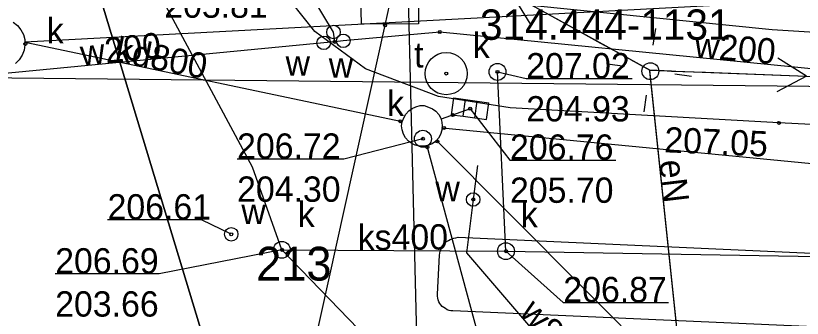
# Model space of a CAD drawing. Extents: x 6512606 to 6513347, y 6022524 to 6022728.
# Drawn here: x 6512795.99 to 6512819.3, y 6022679.94 to 6022688.9 of the extents above; entities that cross this region are included whole.
import ezdxf

# ---------------------------------------------------------------- set-up
doc = ezdxf.new("R2010")
doc.units = 0
for name, color, linetype in [('121-Punkt osnowy szczegółowej', 7, 'Continuous'), ('121-Punkt osnowy szczegółowej-Atr103', 7, 'Continuous'), ('211-numer działki ewidencyjnej', 7, 'Continuous'), ('218-kontur użytku gruntowego', 7, 'Continuous'), ('219-działka ewidencyjna', 7, 'Continuous'), ('4', 7, 'Continuous'), ('Default', 7, 'Continuous'), ('inna obudowa przewodu - sieć elektroenergetyczna (linia)', 7, 'Continuous'), ('inna obudowa przewodu - sieć telekomunikacyjna (linia)', 7, 'Continuous'), ('komora podziemna - przewód kanalizacyjny (powierzchnia)', 7, 'Continuous'), ('komora podziemna - przewód telekomunikacyjny (powierzchnia)', 7, 'Continuous'), ('kratka ściekowa (punkt)', 7, 'Continuous'), ('krawężnik (linia)', 7, 'Continuous'), ('latarnia na słupie lub maszcie (punkt)', 7, 'Continuous'), ('Obszar opracowania', 7, 'Continuous'), ('przewód elektroenergetyczny (linia)', 7, 'Continuous'), ('przewód elektroenergetyczny (linia)-Atr1', 7, 'Continuous'), ('przewód elektroenergetyczny niskiego napięcia (linia)', 7, 'Continuous'), ('przewód elektroenergetyczny niskiego napięcia (linia) - symbol', 7, 'Continuous'), ('przewód gazowy (linia)', 7, 'Continuous'), ('przewód kanalizacyjny (linia)', 7, 'Continuous'), ('przewód kanalizacyjny (linia)-Atr1', 7, 'Continuous'), ('przewód telekomunikacyjny (linia)', 7, 'Continuous'), ('przewód wodociągowy (linia)', 7, 'Continuous'), ('przewód wodociągowy (linia)-Atr1', 7, 'Continuous'), ('punkt o określonej wysokości (sieć kanalizacyjna)', 7, 'Continuous'), ('punkt o określonej wysokości (sieć kanalizacyjna)-Atr2', 7, 'Continuous'), ('punkt o określonej wysokości (sieć kanalizacyjna)-Atr3', 7, 'Continuous'), ('punkt o określonej wysokości (sieć telekomunikacyjna)', 7, 'Continuous'), ('punkt o określonej wysokości (sieć telekomunikacyjna)-Atr3', 7, 'Continuous'), ('punkt o określonej wysokości (sieć wodociągowa)', 7, 'Continuous'), ('punkt o określonej wysokości (sieć wodociągowa)-Atr2', 7, 'Continuous'), ('punkt wysokościowy sztuczny', 7, 'Continuous'), ('punkt wysokościowy sztuczny-Atr2', 7, 'Continuous'), ('słup (punkt)', 7, 'Continuous'), ('właz okrągły - siec kanalizacyjna (punkt)', 7, 'Continuous'), ('właz okrągły - siec kanalizacyjna (punkt)-Atr17', 7, 'Continuous'), ('właz okrągły - siec telekomunikacyjna (punkt)-Atr17', 7, 'Continuous'), ('zasuwa - siec wodociągowa (punkt)', 7, 'Continuous'), ('zasuwa - siec wodociągowa (punkt)-Atr17', 7, 'Continuous')]:
    doc.layers.add(name, color=color, linetype=linetype)

# ---------------------------------------------------------------- blocks, each defined once
blk = doc.blocks.new('PE04')
at = {"layer": 'Default'}
for p, q in [((46.5, 0), (37.84, 5)), ((6.5, 0), (0, 0)), ((6.5, 0), (16.5, 0)), ((16.5, 0), (26.5, 0)), ((26.5, 0), (36.5, 0)), ((36.5, 0), (46.5, 0)), ((46.5, 0), (37.84, -5)), ((46.5, 0), (50, 0))]:
    blk.add_line(p, q, dxfattribs=at)
blk = doc.blocks.new('PW01')
at = {"layer": 'Default'}
blk.add_circle((0, 0), 0.45, dxfattribs=at)
blk = doc.blocks.new('PW02')
at = {"layer": 'Default'}
blk.add_circle((0, 0), 0.45, dxfattribs=at)
blk = doc.blocks.new('US25')
at = {"layer": 'Default'}
blk.add_circle((0, 0), 2, dxfattribs=at)
blk = doc.blocks.new('US22')
at = {"layer": 'Default'}
blk.add_circle((0, 0), 2.5, dxfattribs=at)
blk = doc.blocks.new('US05')
at = {"layer": 'Default'}
for p, q in [((-5.25, -2.5), (-5.25, 2.5)), ((-5.25, 2.5), (-1.75, 2.5)), ((-1.75, -2.5), (-1.75, 2.5)), ((-1.75, 2.5), (1.75, 2.5)), ((1.75, -2.5), (1.75, 2.5)), ((1.75, 2.5), (5.25, 2.5)), ((5.25, -2.5), (5.25, 2.5)), ((-5.25, -2.5), (-1.75, -2.5)), ((-1.75, -2.5), (1.75, -2.5)), ((1.75, -2.5), (5.25, -2.5))]:
    blk.add_line(p, q, dxfattribs=at)
blk = doc.blocks.new('SM011')
at = {"layer": 'Default'}
for p, q in [((-5.3, 5.31), (-8.83, 8.84)), ((5.31, 5.31), (8.84, 8.84)), ((-5.3, -5.3), (-8.83, -8.83)), ((5.31, -5.3), (8.84, -8.83))]:
    blk.add_line(p, q, dxfattribs=at)
blk = doc.blocks.new('SM04')
at = {"layer": 'Default'}
blk.add_circle((0, 0), 2.5, dxfattribs=at)
blk = doc.blocks.new('121')
at = {"layer": 'Default'}
for radius in [6.25, 0.45]:
    blk.add_circle((0, 0), radius, dxfattribs=at)

msp = doc.modelspace()

# ---------------------------------------------------------------- linework, layer by layer
at = {"layer": '218-kontur użytku gruntowego'}
for points in [[(6512798.3, 6022690.12), (6512802.61, 6022675.86)], [(6512802.61, 6022675.86), (6512798.3, 6022690.12)]]:
    msp.add_lwpolyline(points, dxfattribs=at)
at = {"layer": '219-działka ewidencyjna'}
msp.add_lwpolyline([(6512802.61, 6022675.86), (6512798.3, 6022690.12)], dxfattribs=at)
at = {"layer": '4'}
msp.add_lwpolyline([(6512802.61, 6022675.86), (6512798.3, 6022690.12)], dxfattribs=at)
at = {"layer": 'inna obudowa przewodu - sieć elektroenergetyczna (linia)'}
msp.add_lwpolyline([(6512816.36, 6022672.33), (6512816.35, 6022672.33), (6512814.78, 6022687.26)], dxfattribs=at)
at = {"layer": 'inna obudowa przewodu - sieć telekomunikacyjna (linia)'}
msp.add_lwpolyline([(6512803.35, 6022672.37), (6512803.36, 6022672.42), (6512806.94, 6022688.62), (6512806.95, 6022688.66)], dxfattribs=at)
at = {"layer": 'komora podziemna - przewód kanalizacyjny (powierzchnia)'}
msp.add_lwpolyline([(6512795.92, 6022688.71), (6512796.05, 6022688.61), (6512796.15, 6022688.49), (6512796.22, 6022688.35), (6512796.26, 6022688.2), (6512796.26, 6022688.04), (6512796.24, 6022687.88), (6512796.18, 6022687.74), (6512796.1, 6022687.6), (6512795.99, 6022687.49)], dxfattribs=at)
msp.add_lwpolyline([(6512808.63, 6022685.63), (6512808.62, 6022685.51), (6512808.58, 6022685.39), (6512808.52, 6022685.28), (6512808.43, 6022685.18), (6512808.33, 6022685.11), (6512808.21, 6022685.06), (6512808.08, 6022685.04), (6512807.96, 6022685.04), (6512807.83, 6022685.07), (6512807.73, 6022685.12), (6512807.63, 6022685.19), (6512807.54, 6022685.29), (6512807.48, 6022685.4), (6512807.44, 6022685.52), (6512807.43, 6022685.64), (6512807.44, 6022685.76), (6512807.49, 6022685.88), (6512807.55, 6022685.99), (6512807.64, 6022686.09), (6512807.74, 6022686.16), (6512807.85, 6022686.21), (6512807.98, 6022686.24), (6512808.1, 6022686.24), (6512808.23, 6022686.2), (6512808.34, 6022686.15), (6512808.44, 6022686.08), (6512808.53, 6022685.98), (6512808.59, 6022685.87), (6512808.62, 6022685.75)], close=True, dxfattribs=at)
at = {"layer": 'komora podziemna - przewód telekomunikacyjny (powierzchnia)'}
msp.add_lwpolyline([(6512806.24, 6022688.65), (6512806.21, 6022689.9), (6512807.93, 6022689.91), (6512807.93, 6022688.66)], close=True, dxfattribs=at)
at = {"layer": 'krawężnik (linia)'}
for points in [[(6512810.65, 6022686.18), (6512808.52, 6022686.51), (6512806.36, 6022687.33), (6512804.86, 6022688.44), (6512803.82, 6022689.75), (6512802.46, 6022692.22), (6512798.99, 6022700.3), (6512797.428, 6022703.239)], [(6512829.131, 6022685.216), (6512821.11, 6022685.6), (6512818.61, 6022685.73), (6512810.65, 6022686.18)], [(6512822.55, 6022679.56), (6512808.95, 6022680.16), (6512808.89, 6022680.16), (6512808.84, 6022680.17), (6512808.78, 6022680.19), (6512808.73, 6022680.23), (6512808.68, 6022680.26), (6512808.63, 6022680.29), (6512808.59, 6022680.34), (6512808.56, 6022680.38), (6512808.53, 6022680.43), (6512808.51, 6022680.49), (6512808.5, 6022680.54), (6512808.49, 6022680.6), (6512808.49, 6022680.66), (6512808.55, 6022681.81), (6512808.56, 6022681.87), (6512808.57, 6022681.93), (6512808.59, 6022681.98), (6512808.61, 6022682.04), (6512808.64, 6022682.09), (6512808.68, 6022682.14), (6512808.72, 6022682.18), (6512808.76, 6022682.22), (6512808.82, 6022682.25), (6512808.87, 6022682.28), (6512808.93, 6022682.3), (6512808.98, 6022682.32), (6512809.04, 6022682.33), (6512809.1, 6022682.34), (6512822.64, 6022681.73)]]:
    msp.add_lwpolyline(points, dxfattribs=at)
at = {"layer": 'Obszar opracowania'}
msp.add_lwpolyline([(6512710.98, 6022693.84), (6512748.35, 6022694.16), (6512798.11, 6022695.25), (6512807.47, 6022695.46), (6512809.66, 6022606.87), (6512863.71, 6022622.03), (6512875.13, 6022581.36), (6512755.22, 6022535.25), (6512691.61, 6022568.03), (6512709.16, 6022605.16)], close=True, dxfattribs=at)
at = {"layer": 'przewód elektroenergetyczny (linia)'}
for points in [[(6512817.88, 6022671.15), (6512816.35, 6022672.33), (6512814.78, 6022687.29)], [(6512827.998, 6022686.723), (6512793.03, 6022687.08), (6512782.71, 6022686.93), (6512780.71, 6022686.29)]]:
    msp.add_lwpolyline(points, dxfattribs=at)
at = {"layer": 'przewód elektroenergetyczny niskiego napięcia (linia)'}
for points in [[(6512814.78, 6022687.29), (6512803.27, 6022693.63)], [(6512814.78, 6022687.29), (6512827.947, 6022686.79)]]:
    msp.add_lwpolyline(points, dxfattribs=at)
at = {"layer": 'przewód gazowy (linia)'}
msp.add_lwpolyline([(6512808.91, 6022689.46), (6512818.41, 6022688.5), (6512827.069, 6022687.957)], dxfattribs=at)
at = {"layer": 'przewód kanalizacyjny (linia)'}
for points in [[(6512803.88, 6022681.97), (6512803.01, 6022684.42), (6512792.949, 6022703.141)], [(6512823.6, 6022689.9), (6512818.78, 6022689.32), (6512796.26, 6022688.12)], [(6512807.44, 6022685.76), (6512796.27, 6022688.11)], [(6512810.52, 6022681.93), (6512810.27, 6022687.24)], [(6512809.46, 6022686.15), (6512808.6, 6022685.84)], [(6512808.63, 6022685.58), (6512830.439, 6022683.477)], [(6512825.95, 6022667.65), (6512808.46, 6022685.21)], [(6512808.18, 6022685.05), (6512811.35, 6022673.34)], [(6512803.88, 6022681.97), (6512807.28, 6022678.45), (6512809.75, 6022675.66)], [(6512803.88, 6022681.97), (6512810.52, 6022681.93)], [(6512810.52, 6022681.93), (6512831.877, 6022681.566)]]:
    msp.add_lwpolyline(points, dxfattribs=at)
at = {"layer": 'przewód telekomunikacyjny (linia)'}
msp.add_lwpolyline([(6512803.2, 6022671.69), (6512803.36, 6022672.42), (6512806.94, 6022688.62), (6512807.08, 6022689.26)], dxfattribs=at)
at = {"layer": 'przewód wodociągowy (linia)'}
for points in [[(6512805.45, 6022688.13), (6512805.41, 6022688.42), (6512801.5, 6022694.9), (6512799.59, 6022698.41), (6512796.954, 6022703.229)], [(6512828.176, 6022686.486), (6512808.56, 6022688.42), (6512805.7, 6022688.16), (6512805.45, 6022688.13)], [(6512805.45, 6022688.13), (6512805.12, 6022688.1), (6512792.38, 6022686.88), (6512788.46, 6022686.58), (6512782.96, 6022686.75), (6512777.64, 6022686.77), (6512777.27, 6022686.75)], [(6512809.68, 6022684.47), (6512809.55, 6022683.46), (6512809.35, 6022681.88)], [(6512809.35, 6022681.88), (6512813.75, 6022676.76), (6512817.99, 6022672.04), (6512824.14, 6022665.03), (6512827.96, 6022660.57), (6512832.92, 6022654.39), (6512839.85, 6022645.35)], [(6512809.35, 6022681.88), (6512813.75, 6022676.76)]]:
    msp.add_lwpolyline(points, dxfattribs=at)
at = {"layer": 'punkt o określonej wysokości (sieć kanalizacyjna)-Atr2'}
for points in [[(6512810.27, 6022687.24), (6512811.12, 6022687.04), (6512814.261, 6022687.04)], [(6512809.46, 6022686.15), (6512810.64, 6022684.63), (6512813.775, 6022684.63)], [(6512808.06, 6022685.26), (6512805.72, 6022684.66), (6512802.553, 6022684.66)], [(6512803.88, 6022681.97), (6512800.24, 6022681.26), (6512797.163, 6022681.26)], [(6512810.52, 6022681.93), (6512812.22, 6022680.41), (6512815.334, 6022680.41)]]:
    msp.add_lwpolyline(points, dxfattribs=at)
at = {"layer": 'punkt o określonej wysokości (sieć wodociągowa)-Atr2'}
msp.add_lwpolyline([(6512802.38, 6022682.43), (6512801.5, 6022682.86), (6512798.715, 6022682.86)], dxfattribs=at)

# ---------------------------------------------------------------- block references
at = {"layer": '121-Punkt osnowy szczegółowej', "xscale": 0.1, "yscale": 0.10000000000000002}
msp.add_blockref('121', (6512808.75, 6022687.19), dxfattribs=at)
at = {"layer": 'kratka ściekowa (punkt)', "xscale": 0.1, "yscale": 0.10000000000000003, "rotation": -7.674}
msp.add_blockref('US05', (6512809.46, 6022686.15), dxfattribs=at)
at = {"layer": 'latarnia na słupie lub maszcie (punkt)', "xscale": 0.1, "yscale": 0.09999999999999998, "rotation": 36.781}
msp.add_blockref('SM011', (6512814.78, 6022687.29), dxfattribs=at)
at = {"layer": 'przewód elektroenergetyczny niskiego napięcia (linia) - symbol'}
for xscale, yscale, rotation in [(0.10000000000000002, 0.1, 151.153), (0.1, 0.09999999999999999, -2.175000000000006)]:
    msp.add_blockref('PE04', (6512814.78, 6022687.29), dxfattribs=dict(at, xscale=xscale, yscale=yscale, rotation=rotation))
at = {"layer": 'punkt o określonej wysokości (sieć kanalizacyjna)', "xscale": 0.1, "yscale": 0.10000000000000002}
for p in [(6512796.28, 6022688.07), (6512810.27, 6022687.24), (6512808.06, 6022685.26), (6512803.88, 6022681.97), (6512810.52, 6022681.93)]:
    msp.add_blockref('PW01', p, dxfattribs=at)
at = {"layer": 'punkt o określonej wysokości (sieć kanalizacyjna)'}
for p, xscale, yscale, rotation in [((6512808.95, 6022685.96), 0.10000000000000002, 0.1, 20.410000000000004), ((6512809.46, 6022686.15), 0.1, 0.10000000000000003, -7.674), ((6512807.39, 6022685.78), 0.1, 0.10000000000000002, -11.053999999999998), ((6512808.68, 6022685.58), 0.09999999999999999, 0.09999999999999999, -4.699), ((6512808.19, 6022685.01), 0.09999999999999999, 0.1, -74.074), ((6512808.49, 6022685.18), 0.1, 0.09999999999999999, -44.297000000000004)]:
    msp.add_blockref('PW01', p, dxfattribs=dict(at, xscale=xscale, yscale=yscale, rotation=rotation))
at = {"layer": 'punkt o określonej wysokości (sieć telekomunikacyjna)', "xscale": 0.09999999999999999, "yscale": 0.10000000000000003, "rotation": 78.325}
msp.add_blockref('PW01', (6512806.94, 6022688.62), dxfattribs=at)
at = {"layer": 'punkt o określonej wysokości (sieć wodociągowa)', "xscale": 0.1, "yscale": 0.10000000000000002}
for p in [(6512808.56, 6022688.42), (6512805.45, 6022688.13)]:
    msp.add_blockref('PW01', p, dxfattribs=at)
at = {"layer": 'punkt o określonej wysokości (sieć wodociągowa)', "xscale": 0.10000000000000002, "yscale": 0.10000000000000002}
for p, rotation in [((6512809.55, 6022683.46), 0.8779999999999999), ((6512802.38, 6022682.43), -88.901)]:
    msp.add_blockref('PW01', p, dxfattribs=dict(at, rotation=rotation))
at = {"layer": 'punkt wysokościowy sztuczny', "xscale": 0.1, "yscale": 0.10000000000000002}
msp.add_blockref('PW02', (6512818.61, 6022685.73), dxfattribs=at)
at = {"layer": 'słup (punkt)', "xscale": 0.1, "yscale": 0.10000000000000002}
msp.add_blockref('SM04', (6512814.8, 6022687.26), dxfattribs=at)
at = {"layer": 'właz okrągły - siec kanalizacyjna (punkt)', "xscale": 0.1, "yscale": 0.10000000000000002}
for p in [(6512810.27, 6022687.24), (6512808.06, 6022685.26), (6512803.88, 6022681.97), (6512810.52, 6022681.93)]:
    msp.add_blockref('US22', p, dxfattribs=at)
at = {"layer": 'zasuwa - siec wodociągowa (punkt)'}
for p, xscale, yscale, rotation in [((6512805.41, 6022688.42), 0.10000000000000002, 0.1, -58.075), ((6512805.7, 6022688.16), 0.10000000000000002, 0.1, 5.988), ((6512805.12, 6022688.1), 0.09999999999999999, 0.1, 6.911), ((6512809.55, 6022683.46), 0.10000000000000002, 0.10000000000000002, 0.8779999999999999), ((6512802.38, 6022682.43), 0.10000000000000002, 0.10000000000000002, -88.901)]:
    msp.add_blockref('US25', p, dxfattribs=dict(at, xscale=xscale, yscale=yscale, rotation=rotation))

# ---------------------------------------------------------------- texts
at = {"layer": '121-Punkt osnowy szczegółowej-Atr103'}
msp.add_text('314.444-1131', height=0.9, dxfattribs=at).set_placement((6512809.75, 6022688.19))
at = {"layer": '211-numer działki ewidencyjnej'}
msp.add_text('213', height=1, dxfattribs=at).set_placement((6512803.12, 6022681.06))
at = {"layer": '4'}
msp.add_text('213', height=1, dxfattribs=at).set_placement((6512803.12, 6022681.06))
at = {"layer": 'przewód elektroenergetyczny (linia)-Atr1'}
msp.add_text('eN', height=0.75, rotation=276.794, dxfattribs=at).set_placement((6512815.06, 6022684.6))
at = {"layer": 'przewód kanalizacyjny (linia)-Atr1'}
for s, rotation, p in [('kd800', 348.937, (6512798.9, 6022687.55)), ('ks400', 0.431, (6512806.13, 6022681.96))]:
    msp.add_text(s, height=0.75, rotation=rotation, dxfattribs=at).set_placement(p)
at = {"layer": 'przewód wodociągowy (linia)-Atr1'}
for s, rotation, p in [('w200', 6.281, (6512797.95, 6022687.41)), ('w200', 355.172, (6512816.09, 6022687.67)), ('w80-n', 311.432, (6512810.89, 6022680.09))]:
    msp.add_text(s, height=0.75, rotation=rotation, dxfattribs=at).set_placement(p)
at = {"layer": 'punkt o określonej wysokości (sieć kanalizacyjna)-Atr2'}
for s, p in [('207.02', (6512811.12, 6022687.048)), ('206.72', (6512802.553, 6022684.668)), ('206.76', (6512810.64, 6022684.638)), ('206.69', (6512797.163, 6022681.268)), ('206.87', (6512812.22, 6022680.418))]:
    msp.add_text(s, height=0.75, dxfattribs=at).set_placement(p)
at = {"layer": 'punkt o określonej wysokości (sieć kanalizacyjna)-Atr3'}
for s, p in [('204.93', (6512811.12, 6022685.772)), ('204.30', (6512802.553, 6022683.393)), ('205.70', (6512810.64, 6022683.362)), ('203.66', (6512797.163, 6022679.992))]:
    msp.add_text(s, height=0.75, dxfattribs=at).set_placement(p)
at = {"layer": 'punkt o określonej wysokości (sieć telekomunikacyjna)-Atr3'}
msp.add_text('205.81', height=0.75, dxfattribs=at).set_placement((6512800.393, 6022688.843))
at = {"layer": 'punkt o określonej wysokości (sieć wodociągowa)-Atr2'}
msp.add_text('206.61', height=0.75, dxfattribs=at).set_placement((6512798.715, 6022682.868))
at = {"layer": 'punkt wysokościowy sztuczny-Atr2'}
msp.add_text('207.05', height=0.75, rotation=357.554, dxfattribs=at).set_placement((6512815.2, 6022684.86))
at = {"layer": 'właz okrągły - siec kanalizacyjna (punkt)-Atr17'}
for p in [(6512796.91, 6022688.09), (6512809.54, 6022687.65), (6512807, 6022685.93), (6512804.35, 6022682.65), (6512810.96, 6022682.64)]:
    msp.add_text('k', height=0.75, dxfattribs=at).set_placement(p)
at = {"layer": 'właz okrągły - siec telekomunikacyjna (punkt)-Atr17'}
msp.add_text('t', height=0.75, dxfattribs=at).set_placement((6512807.8, 6022687.37))
at = {"layer": 'zasuwa - siec wodociągowa (punkt)-Atr17'}
for p in [(6512803.99, 6022687.13), (6512805.27, 6022687.07), (6512808.43, 6022683.41), (6512802.68, 6022682.73)]:
    msp.add_text('w', height=0.75, dxfattribs=at).set_placement(p)

doc.saveas('drawing.dxf')
